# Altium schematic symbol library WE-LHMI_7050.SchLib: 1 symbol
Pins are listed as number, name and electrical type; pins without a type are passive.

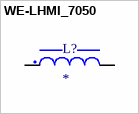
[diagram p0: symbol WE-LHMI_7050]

## WE-LHMI_7050
designator L?
4.7ÂµH Shielded Molded Inductor 5A 30.8mOhm Max Nonstandard; MF: WÃ¼rth Elektronik; MP: 74437349047
footprint WE-LHMI_7050
pins: 1, 2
